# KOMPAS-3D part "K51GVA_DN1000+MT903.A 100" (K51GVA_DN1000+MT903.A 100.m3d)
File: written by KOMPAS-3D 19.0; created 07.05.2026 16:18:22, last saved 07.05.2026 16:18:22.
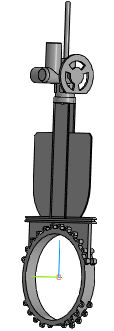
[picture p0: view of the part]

Document properties: Автор: Энергия; Полное имя файла: ..\K51GVA_DN50-DN1000+MT903.A\K51GVA_DN1000+MT903.A 100.a3d

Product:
- Part/product: K51GVA_DN1000+MT903.A 100
    Масса: 872.202

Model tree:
1. Операция без истории:1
